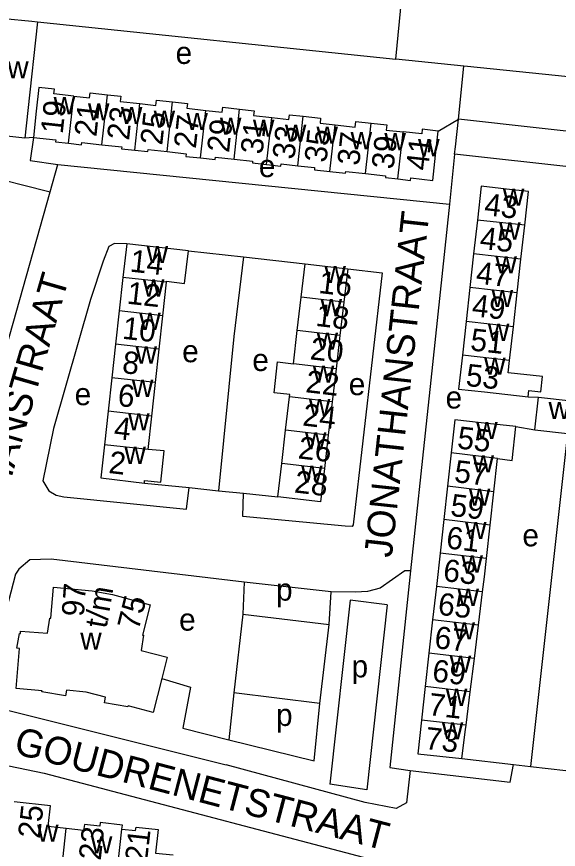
# Model space of a CAD drawing. Extents: x 161936 to 163647, y 386450 to 388633.
# Drawn here: x 162391.5 to 162488.9, y 387951 to 388100.7 of the extents above; entities that cross this region are included whole.
import ezdxf

# ---------------------------------------------------------------- set-up
doc = ezdxf.new("R2010")
doc.units = 0
for name, color, linetype in [('BLT_Basislijn', 7, 'Continuous'), ('BLT_Bebouwing', 7, 'Continuous'), ('BLT_Centroide', 7, 'Continuous'), ('BLT_Huisnummer', 7, 'Continuous'), ('BLT_Huisnummer_ tussenligend', 7, 'Continuous'), ('BLT_Huisnummer_reeks', 7, 'Continuous'), ('BLT_Onderverdeling_panden', 7, 'Continuous'), ('BLT_Straatnaam', 7, 'Continuous'), ('BLT_Vlakafsluiter', 7, 'Continuous')]:
    doc.layers.add(name, color=color, linetype=linetype)

msp = doc.modelspace()

# ---------------------------------------------------------------- linework, layer by layer
at = {"layer": 'BLT_Basislijn'}
for p, q in [((162459.69, 388093.03), (162462.15, 388118.33)), ((162395.28, 388099.73), (162459.69, 388093.03)), ((162471.95, 388091.77), (162459.69, 388093.03)), ((162470.99, 388082.26), (162471.95, 388091.77)), ((162394.56, 388078.99), (162393.03, 388078.83)), ((162470.29, 388075.98), (162469.34, 388066.98)), ((162397.59, 388069.19), (162398.96, 388074.13)), ((162398.96, 388074.13), (162469.34, 388066.98)), ((162469.34, 388066.98), (162465.86, 388034.19)), ((162422.43, 388058.6), (162432.35, 388057.49)), ((162432.35, 388057.49), (162443.39, 388056.25)), ((162465.86, 388034.19), (162465.27, 388028.63)), ((162483.48, 388032.36), (162485.34, 388032.29)), ((162465.27, 388028.63), (162462.35, 388001.06)), ((162481.29, 388027), (162484.69, 388026.45)), ((162490.61, 388025.79), (162483.95, 387965.94)), ((162414.5, 388016.86), (162422.55, 388016.03)), ((162422.55, 388016.03), (162427.83, 388015.48)), ((162427.83, 388015.48), (162432.32, 388015.02)), ((162432.32, 388015.02), (162438.49, 388014.38)), ((162447.71, 387991.45), (162448.08, 387997.33)), ((162451.52, 387995.81), (162447.84, 387962.72)), ((162458.16, 387995), (162451.52, 387995.81)), ((162458.16, 387995), (162454.49, 387961.74)), ((162446.05, 387977.21), (162447.71, 387991.45)), ((162429.69, 387970.73), (162445.04, 387966.96)), ((162471.61, 387967.33), (162480.88, 387966.28)), ((162480.88, 387966.28), (162483.95, 387965.94)), ((162483.95, 387965.94), (162490.26, 387965.22)), ((162454.49, 387961.74), (162447.84, 387962.72))]:
    msp.add_line(p, q, dxfattribs=at)
for points in [[(162522.22, 388086.64), (162472.61, 388091.7), (162471.95, 388091.77)], [(162394.56, 388078.99), (162393.98, 388074.82), (162398.96, 388074.13)], [(162374.5, 388074.61), (162384.11, 388072.61), (162392.6, 388070.43), (162397.59, 388069.19)], [(162382.23, 388015.02), (162382.33, 388015.37), (162397.59, 388069.19)], [(162411.33, 388059.83), (162409.14, 388059.89), (162408.09, 388059.36), (162407.07, 388056.73), (162404.84, 388049.87), (162398.17, 388026.67), (162396.24, 388017.24), (162397.31, 388015.45), (162398.63, 388014.69), (162400, 388014.37), (162422.06, 388012.16), (162422.55, 388016.03)], [(162432.35, 388057.49), (162430.58, 388043.17), (162427.83, 388015.48)], [(162451.07, 388055.35), (162457.27, 388054.66), (162452.07, 388009.33), (162451.84, 388009.07), (162450.63, 388009.12), (162432.19, 388010.87), (162432.32, 388015.02)], [(162432.42, 387999.04), (162397.73, 388003.15), (162393.92, 388003.07), (162391.95, 388001.41), (162391.31, 388000.46), (162386.59, 387982.45), (162386.53, 387981.29)], [(162462.35, 388001.06), (162461.35, 388001.08), (162456.89, 387997.98), (162454.6, 387997.39), (162452.47, 387997.24), (162448.08, 387997.33)], [(162462.35, 388001.06), (162458.61, 387965.72), (162462.29, 387965.22)], [(162432.42, 387999.04), (162432.19, 387993.32)], [(162448.08, 387997.33), (162432.42, 387999.04)], [(162432.19, 387993.32), (162430.58, 387979.14)], [(162432.19, 387993.32), (162447.71, 387991.45)], [(162417.62, 387981.76), (162422.8, 387980.18), (162421.44, 387972.78), (162429.69, 387970.73)], [(162386.53, 387981.29), (162386.38, 387978.17), (162388.92, 387976.28), (162429.23, 387966.2)], [(162430.58, 387979.14), (162429.69, 387970.73)], [(162446.05, 387977.21), (162430.58, 387979.14)], [(162445.04, 387966.96), (162446.05, 387977.21)], [(162322.3, 387973.74), (162372.21, 387968.81), (162383.73, 387967.34), (162396.47, 387964.74), (162462.94, 387947.25), (162508.45, 387942.15), (162508.66, 387941.36), (162504.97, 387908.35)], [(162462.29, 387965.22), (162461.61, 387959.36), (162459.76, 387958.34), (162454.21, 387959.43), (162429.23, 387966.2)], [(162462.29, 387965.22), (162480.29, 387963.11), (162480.88, 387966.28)]]:
    msp.add_lwpolyline(points, dxfattribs=at)
at = {"layer": 'BLT_Bebouwing'}
for p, q in [((162495.79, 388073.14), (162470.29, 388075.98)), ((162474.38, 388064.13), (162473.7, 388058.06)), ((162482.2, 388057.11), (162482.88, 388063.19)), ((162411.33, 388059.83), (162410.66, 388053.82)), ((162422.43, 388058.6), (162411.33, 388059.83)), ((162473.7, 388058.06), (162473.03, 388051.98)), ((162481.53, 388051.03), (162482.2, 388057.11)), ((162442.69, 388050.27), (162443.39, 388056.25)), ((162443.39, 388056.25), (162451.07, 388055.35)), ((162451.07, 388055.35), (162450.37, 388049.37)), ((162410.66, 388053.82), (162409.99, 388047.81)), ((162417.83, 388046.94), (162418.5, 388052.96)), ((162473.03, 388051.98), (162472.35, 388045.9)), ((162480.85, 388044.96), (162481.53, 388051.03)), ((162441.99, 388044.29), (162442.69, 388050.27)), ((162450.37, 388049.37), (162449.67, 388043.39)), ((162409.99, 388047.81), (162409.33, 388041.79)), ((162417.16, 388040.92), (162417.83, 388046.94)), ((162472.35, 388045.9), (162471.68, 388039.83)), ((162480.18, 388038.88), (162480.85, 388044.96)), ((162441.29, 388038.31), (162441.99, 388044.29)), ((162449.67, 388043.39), (162448.97, 388037.41)), ((162409.33, 388041.79), (162408.66, 388035.77)), ((162416.5, 388034.91), (162417.16, 388040.92)), ((162471.68, 388039.83), (162471, 388033.75)), ((162448.97, 388037.41), (162448.27, 388031.43)), ((162408.66, 388035.77), (162408, 388029.76)), ((162415.83, 388028.89), (162416.5, 388034.91)), ((162439.89, 388026.34), (162440.59, 388032.33)), ((162448.27, 388031.43), (162447.57, 388025.45)), ((162408, 388029.76), (162407.33, 388023.74)), ((162415.17, 388022.88), (162415.83, 388028.89)), ((162470.33, 388028.22), (162469.67, 388022.28)), ((162439.19, 388020.36), (162439.89, 388026.34)), ((162447.57, 388025.45), (162446.87, 388019.46)), ((162469.67, 388022.28), (162469, 388016.28)), ((162477.34, 388015.29), (162478.01, 388021.29)), ((162438.49, 388014.38), (162439.19, 388020.36)), ((162469, 388016.28), (162468.33, 388010.28)), ((162476.68, 388009.29), (162477.34, 388015.29)), ((162468.33, 388010.28), (162467.66, 388004.27)), ((162476.01, 388003.29), (162476.68, 388009.29)), ((162467.66, 388004.27), (162467, 387998.27)), ((162467, 387998.27), (162466.33, 387992.27)), ((162474.57, 387991.3), (162475.31, 387997.29)), ((162466.33, 387992.27), (162465.66, 387986.27)), ((162473.83, 387985.31), (162474.57, 387991.3)), ((162465.66, 387986.27), (162464.99, 387980.27)), ((162473.09, 387979.32), (162473.83, 387985.31)), ((162464.99, 387980.27), (162464.33, 387974.27)), ((162472.35, 387973.33), (162473.09, 387979.32))]:
    msp.add_line(p, q, dxfattribs=at)
for points in [[(162393.03, 388078.83), (162387.07, 388079.48), (162389.32, 388100.37)], [(162389.32, 388100.37), (162394.29, 388099.84), (162395.28, 388099.73)], [(162395.28, 388099.73), (162393.57, 388083.81), (162393.03, 388078.83)], [(162401.81, 388086.4), (162398.24, 388086.79), (162398.34, 388087.66), (162395.54, 388087.97), (162395.07, 388083.68), (162394.56, 388078.99)], [(162401.81, 388086.4), (162404.64, 388086.09), (162404.74, 388086.97), (162407.85, 388086.63)], [(162407.85, 388086.63), (162410.25, 388086.37), (162410.15, 388085.44), (162413.69, 388085.05)], [(162413.69, 388085.05), (162416.58, 388084.74), (162416.68, 388085.66), (162419.57, 388085.35)], [(162419.57, 388085.35), (162422.24, 388085.05), (162422.15, 388084.21), (162425.53, 388083.84)], [(162425.53, 388083.84), (162428.5, 388083.51), (162428.59, 388084.4), (162431.6, 388084.07)], [(162431.6, 388084.07), (162434.23, 388083.78), (162434.13, 388082.9), (162437.41, 388082.54)], [(162437.41, 388082.54), (162440.49, 388082.21), (162440.58, 388083.06), (162443.06, 388082.79)], [(162443.06, 388082.79), (162446.19, 388082.45), (162446.09, 388081.54), (162448.79, 388081.24)], [(162470.29, 388075.98), (162470.44, 388077.3), (162470.99, 388082.26)], [(162514.13, 388071.09), (162514.83, 388077.37), (162500, 388079.02), (162470.99, 388082.26)], [(162448.79, 388081.24), (162452.43, 388080.84), (162452.53, 388081.81), (162455.28, 388081.51)], [(162455.28, 388081.51), (162458.07, 388081.21), (162457.97, 388080.3), (162461.03, 388079.96)], [(162467.33, 388080.12), (162464.48, 388080.43), (162464.39, 388079.6), (162461.03, 388079.96)], [(162394.56, 388078.99), (162398.58, 388078.55), (162398.54, 388078.18), (162400.88, 388077.93)], [(162460.1, 388071.51), (162462.37, 388071.26), (162462.41, 388071.69), (162466.36, 388071.25), (162466.86, 388075.77), (162467.33, 388080.12)], [(162400.88, 388077.93), (162403.23, 388077.67), (162403.27, 388078.06), (162406.86, 388077.67)], [(162406.86, 388077.67), (162410.46, 388077.27), (162410.42, 388076.94), (162412.77, 388076.68)], [(162412.77, 388076.68), (162415.12, 388076.43), (162415.17, 388076.8), (162418.6, 388076.42)], [(162418.6, 388076.42), (162422.03, 388076.05), (162421.97, 388075.57), (162424.6, 388075.28)], [(162424.6, 388075.28), (162427.22, 388074.99), (162427.27, 388075.44), (162430.62, 388075.07)], [(162430.62, 388075.07), (162433.97, 388074.7), (162433.93, 388074.38), (162436.48, 388074.1)], [(162436.48, 388074.1), (162439.03, 388073.82), (162439.07, 388074.21), (162442.09, 388073.88)], [(162442.09, 388073.88), (162445.11, 388073.55), (162445.07, 388073.16), (162447.87, 388072.85)], [(162447.87, 388072.85), (162450.68, 388072.54), (162450.71, 388072.87), (162454.29, 388072.48)], [(162454.29, 388072.48), (162457.87, 388072.08), (162457.83, 388071.76), (162460.1, 388071.51)], [(162475.05, 388070.2), (162474.38, 388064.13)], [(162482.88, 388063.19), (162483.55, 388069.26), (162479.64, 388069.69), (162475.05, 388070.2)], [(162418.5, 388052.96), (162418.51, 388053.12), (162421.73, 388052.74), (162422.43, 388058.6)], [(162440.59, 388032.33), (162440.64, 388032.76), (162437.82, 388033.1), (162438.47, 388038.63), (162441.29, 388038.31)], [(162483.48, 388032.36), (162483.61, 388033.52), (162485.79, 388033.28), (162486.09, 388035.99), (162479.93, 388036.67), (162480.18, 388038.88)], [(162471, 388033.75), (162475.64, 388033.23), (162483.48, 388032.36)], [(162484.69, 388026.45), (162485.34, 388032.29)], [(162485.34, 388032.29), (162491.26, 388031.64)], [(162481.29, 388027), (162475.08, 388027.69), (162470.33, 388028.22)], [(162478.01, 388021.29), (162480.62, 388020.9), (162481.29, 388027)], [(162484.69, 388026.45), (162490.61, 388025.79)], [(162407.33, 388023.74), (162406.67, 388017.78), (162414.5, 388016.86)], [(162414.5, 388016.86), (162414.55, 388017.31), (162417.44, 388016.99), (162418.07, 388022.66), (162415.17, 388022.88)], [(162446.87, 388019.46), (162446.17, 388013.48), (162438.49, 388014.38)], [(162475.31, 387997.29), (162475.65, 388000), (162476.01, 388003.29)], [(162391.48, 387979.96), (162392.03, 387987.14), (162391.58, 387987.21), (162392.03, 387989.82), (162392.23, 387989.79), (162392.26, 387990.24), (162397.06, 387989.88), (162397.52, 387992.6), (162397.71, 387992.59), (162398.18, 387998.16), (162405.12, 387997.46), (162408.8, 387996.81), (162415.55, 387994.99), (162414.17, 387989.52), (162414.37, 387989.49), (162413.9, 387986.75), (162418.58, 387985.57), (162417.62, 387981.76)], [(162417.62, 387981.76), (162416.09, 387975.63), (162411.58, 387976.82), (162411.55, 387976.62), (162407.31, 387977.36), (162407.49, 387978.38), (162404.03, 387979.3), (162400.5, 387979.66), (162400.34, 387978.64), (162396.09, 387979.33), (162396.13, 387979.53), (162391.48, 387979.96)], [(162464.33, 387974.27), (162463.65, 387968.22), (162471.61, 387967.33)], [(162471.61, 387967.33), (162472.26, 387972.58), (162472.35, 387973.33)], [(162400.46, 387954.77), (162397.19, 387955.12), (162397.62, 387958.82), (162391.11, 387959.57)], [(162410.48, 387954.66), (162410.57, 387955.37), (162406.55, 387955.84), (162406.48, 387955.19), (162403.71, 387955.5), (162403.58, 387954.43), (162400.46, 387954.77)], [(162410.48, 387954.66), (162412.93, 387954.39), (162413.01, 387955.04), (162416.99, 387954.57), (162416.5, 387950.33), (162419.69, 387950.06)]]:
    msp.add_lwpolyline(points, dxfattribs=at)
at = {"layer": 'BLT_Onderverdeling_panden'}
for p, q in [((162400.88, 388077.93), (162401.81, 388086.4)), ((162406.86, 388077.67), (162407.85, 388086.63)), ((162412.77, 388076.68), (162413.69, 388085.05)), ((162418.6, 388076.42), (162419.57, 388085.35)), ((162424.6, 388075.28), (162425.53, 388083.84)), ((162430.62, 388075.07), (162431.6, 388084.07)), ((162436.48, 388074.1), (162437.41, 388082.54)), ((162442.09, 388073.88), (162443.06, 388082.79)), ((162447.87, 388072.85), (162448.79, 388081.24)), ((162454.29, 388072.48), (162455.28, 388081.51)), ((162460.1, 388071.51), (162461.03, 388079.96)), ((162482.88, 388063.19), (162474.38, 388064.13)), ((162482.2, 388057.11), (162473.7, 388058.06)), ((162418.5, 388052.96), (162410.66, 388053.82)), ((162481.53, 388051.03), (162473.03, 388051.98)), ((162450.37, 388049.37), (162442.69, 388050.27)), ((162417.83, 388046.94), (162409.99, 388047.81)), ((162480.85, 388044.96), (162472.35, 388045.9)), ((162449.67, 388043.39), (162441.99, 388044.29)), ((162417.16, 388040.92), (162409.33, 388041.79)), ((162480.18, 388038.88), (162471.68, 388039.83)), ((162448.97, 388037.41), (162441.29, 388038.31)), ((162416.5, 388034.91), (162408.66, 388035.77)), ((162448.27, 388031.43), (162440.59, 388032.33)), ((162415.83, 388028.89), (162408, 388029.76)), ((162447.57, 388025.45), (162439.89, 388026.34)), ((162415.17, 388022.88), (162407.33, 388023.74)), ((162478.01, 388021.29), (162469.67, 388022.28)), ((162446.87, 388019.46), (162439.19, 388020.36)), ((162477.34, 388015.29), (162469, 388016.28)), ((162476.68, 388009.29), (162468.33, 388010.28)), ((162476.01, 388003.29), (162467.66, 388004.27)), ((162475.31, 387997.29), (162467, 387998.27)), ((162474.57, 387991.3), (162466.33, 387992.27)), ((162473.83, 387985.31), (162465.66, 387986.27)), ((162473.09, 387979.32), (162464.99, 387980.27)), ((162472.35, 387973.33), (162464.33, 387974.27)), ((162399.51, 387946.23), (162400.46, 387954.77)), ((162409.08, 387942.64), (162410.48, 387954.66))]:
    msp.add_line(p, q, dxfattribs=at)
at = {"layer": 'BLT_Vlakafsluiter'}
msp.add_line((162467.33, 388080.12), (162470.99, 388082.26), dxfattribs=at)

# ---------------------------------------------------------------- texts
at = {"layer": 'BLT_Centroide'}
for s, p in [('e', (162420.12, 388092.18)), ('w', (162389.84, 388089.59)), ('w', (162398.19, 388083.14)), ('w', (162404.36, 388082.03)), ('w', (162410.28, 388081.36)), ('w', (162416.17, 388080.73)), ('w', (162422.06, 388080.31)), ('w', (162428.09, 388079.45)), ('w', (162434.02, 388079.09)), ('w', (162439.77, 388078.2)), ('w', (162445.44, 388077.83)), ('w', (162451.58, 388076.86)), ('w', (162457.66, 388076.67)), ('w', (162463.72, 388075.59)), ('e', (162435.09, 388071.85)), ('w', (162478.96, 388066.69)), ('w', (162478.29, 388060.62)), ('w', (162414.91, 388056.38)), ('w', (162477.62, 388054.53)), ('w', (162446.88, 388052.81)), ('w', (162414.24, 388050.38)), ('w', (162476.94, 388048.47)), ('w', (162446.18, 388046.84)), ('w', (162413.58, 388044.38)), ('w', (162476.26, 388042.41)), ('w', (162445.48, 388040.84)), ('e', (162421.3, 388038.57)), ('w', (162412.91, 388038.34)), ('e', (162433.91, 388036.99)), ('w', (162475.59, 388036.31)), ('w', (162444.78, 388034.88)), ('e', (162451.25, 388032.65)), ('e', (162401.97, 388030.85)), ('w', (162412.25, 388032.34)), ('e', (162468.66, 388030.25)), ('w', (162444.08, 388028.88)), ('w', (162487.17, 388028.35)), ('w', (162411.58, 388026.31)), ('w', (162474.16, 388024.75)), ('w', (162443.38, 388022.91)), ('w', (162410.91, 388020.31)), ('w', (162473.51, 388018.78)), ('w', (162442.69, 388016.94)), ('w', (162472.84, 388012.78)), ('w', (162472.16, 388006.78)), ('e', (162482.47, 388005.48)), ('w', (162471.51, 388000.78)), ('p', (162438.18, 387995.72)), ('w', (162470.8, 387994.78)), ('e', (162420.75, 387990.33)), ('w', (162470.1, 387988.78)), ('w', (162402.97, 387986.91)), ('p', (162451.76, 387981.93)), ('w', (162469.4, 387982.78)), ('w', (162468.7, 387976.81)), ('p', (162438.18, 387973.2)), ('w', (162467.99, 387970.81)), ('w', (162395.22, 387952.41)), ('w', (162404.89, 387950.31))]:
    msp.add_text(s, height=4, dxfattribs=at).set_placement(p)
at = {"layer": 'BLT_Huisnummer'}
for s, rotation, p in [('19', 83.7482, (162399.81, 388079.5)), ('23', 83.7514, (162411.74, 388078.36)), ('27', 83.7458, (162423.75, 388076.88)), ('31', 83.7492, (162435.75, 388075.83)), ('35', 83.7412, (162447.23, 388074.35)), ('41', 83.735, (162465.5, 388072.91)), ('43', 353.6576, (162475.49, 388065.01)), ('14', 353.6847, (162411.79, 388054.87)), ('47', 353.6576, (162474, 388052.72)), ('16', 353.3295, (162445.7, 388051.03)), ('10', 353.6847, (162410.43, 388042.8)), ('20', 353.3343, (162444.16, 388039.11)), ('53', 353.6635, (162472.17, 388034.34)), ('6', 353.6847, (162409.58, 388030.74)), ('24', 353.3326, (162442.83, 388027.21)), ('55', 353.2837, (162470.63, 388023.1)), ('2', 353.3122, (162407.96, 388018.68)), ('28', 353.33, (162441.34, 388015.18)), ('59', 353.2789, (162469.4, 388010.97)), ('63', 353.2836, (162468.09, 387999.27)), ('67', 353.2787, (162466.52, 387987.2)), ('73', 353.6622, (162464.84, 387969.07)), ('25', 83.6747, (162395.72, 387952.86)), ('21', 83.6753, (162414.97, 387948.54))]:
    msp.add_text(s, height=4, rotation=rotation, dxfattribs=at).set_placement(p)
at = {"layer": 'BLT_Huisnummer_ tussenligend'}
for s, rotation, p in [('21', 83.7482, (162405.87, 388079)), ('25', 83.7514, (162417.71, 388077.48)), ('29', 83.7458, (162429.72, 388076.15)), ('33', 83.7492, (162441.47, 388074.92)), ('37', 83.7412, (162453.13, 388073.8)), ('39', 83.7412, (162459.3, 388073.14)), ('45', 353.6576, (162474.69, 388058.97)), ('12', 353.6847, (162411.25, 388049.11)), ('49', 353.6576, (162473.27, 388046.87)), ('18', 353.3295, (162445.17, 388045.12)), ('51', 353.6576, (162472.98, 388040.71)), ('8', 353.6847, (162410.4, 388036.65)), ('22', 353.3343, (162443.37, 388033.2)), ('4', 353.3122, (162408.89, 388024.86)), ('26', 353.3326, (162442.02, 388021.3)), ('57', 353.2837, (162470.08, 388017.05)), ('61', 353.2789, (162468.64, 388005.14)), ('65', 353.2836, (162467.15, 387993.22)), ('69', 353.2787, (162466.13, 387981.22)), ('71', 353.2787, (162465.44, 387975.18)), ('23', 83.6753, (162406.65, 387948.94))]:
    msp.add_text(s, height=4, rotation=rotation, dxfattribs=at).set_placement(p)
at = {"layer": 'BLT_Huisnummer_reeks'}
for s, rotation, p in [('97', 85.6629, (162403.6, 387992.76)), ('t/m', 80.3107, (162407.7, 387990.62)), ('75', 75.9041, (162413.46, 387990.26))]:
    msp.add_text(s, height=4, rotation=rotation, dxfattribs=at).set_placement(p)
at = {"layer": 'BLT_Straatnaam'}
for s, height, rotation, p in [('JONATHANSTRAAT', 5, 83.7741, (162458.98, 388003.34)), ('JONATHANSTRAAT', 4.9999, 73.8809, (162383.67, 387993.71)), ('GOUDRENETSTRAAT', 5, 345.3286, (162390.83, 387968.3))]:
    msp.add_text(s, height=height, rotation=rotation, dxfattribs=at).set_placement(p)

doc.saveas('drawing.dxf')
